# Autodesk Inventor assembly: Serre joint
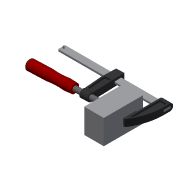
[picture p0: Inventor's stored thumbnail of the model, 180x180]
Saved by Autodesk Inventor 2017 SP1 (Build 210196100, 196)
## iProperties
Created: 2015-12
Part Number: Serre joint
Material: Générique
Document SubType Name: Assembly
Designer: Papa
Author: Papa
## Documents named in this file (6)
- H:\Consmec\1si\Cours\Leçon 04 - Schématisation\04-02-TD Schematisation\04-02-04-TD4Serre Joint\04-02-04-02-SerreJoint 3D\Serre joint.iam
- H:\Consmec\1si\Cours\Leçon 04 - Schématisation\04-02-TD Schematisation\04-02-04-TD4Serre Joint\04-02-04-02-SerreJoint 3D\ensemble fixe.iam
- H:\Consmec\1si\Cours\Leçon 04 - Schématisation\04-02-TD Schematisation\04-02-04-TD4Serre Joint\04-02-04-02-SerreJoint 3D\04-Mors_mobile.ipt
- H:\Consmec\1si\Cours\Leçon 04 - Schématisation\04-02-TD Schematisation\04-02-04-TD4Serre Joint\04-02-04-02-SerreJoint 3D\ensemble mobile.iam
- H:\Consmec\1si\Cours\Leçon 04 - Schématisation\04-02-TD Schematisation\04-02-04-TD4Serre Joint\04-02-04-02-SerreJoint 3D\05-Patin.ipt
- H:\Consmec\1si\Cours\Leçon 04 - Schématisation\04-02-TD Schematisation\04-02-04-TD4Serre Joint\04-02-04-02-SerreJoint 3D\08-Pièce.ipt
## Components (5 placed, 5 different names)
1. ensemble fixe:1 [sub-assembly] — Placage:1, Placage:4, Affleurement:1, Placage:5, Placage:8, Placage:10
2. 04-Mors_mobile:1 — Placage:1, Placage:3, Placage:8, Placage:10
3. ensemble mobile:1 [sub-assembly] — Placage:3, Placage:7, Logement:1
4. 05-Patin:1 — Placage:7, Placage:9, Logement:1, Placage:11
5. 08-Pièce:1 — Placage:4, Affleurement:1, Placage:5, Placage:9, Placage:11
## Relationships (11: Mate 9, Flush 1, Insert 1)
- Placage:1 [Mate]: ensemble fixe:1 ↔ 04-Mors_mobile:1
- Placage:3 [Mate]: 04-Mors_mobile:1 ↔ ensemble mobile:1
- Placage:4 [Mate]: ensemble fixe:1 ↔ 08-Pièce:1
- Affleurement:1 [Flush]: ensemble fixe:1 ↔ 08-Pièce:1
- Placage:5 [Mate]: ensemble fixe:1 ↔ 08-Pièce:1
- Placage:7 [Mate]: ensemble mobile:1 ↔ 05-Patin:1
- Placage:8 [Mate]: ensemble fixe:1 ↔ 04-Mors_mobile:1
- Placage:9 [Mate]: 05-Patin:1 ↔ 08-Pièce:1
- Logement:1 [Insert]: ensemble mobile:1 ↔ 05-Patin:1
- Placage:10 [Mate]: ensemble fixe:1 ↔ 04-Mors_mobile:1
- Placage:11 [Mate]: 05-Patin:1 ↔ 08-Pièce:1
